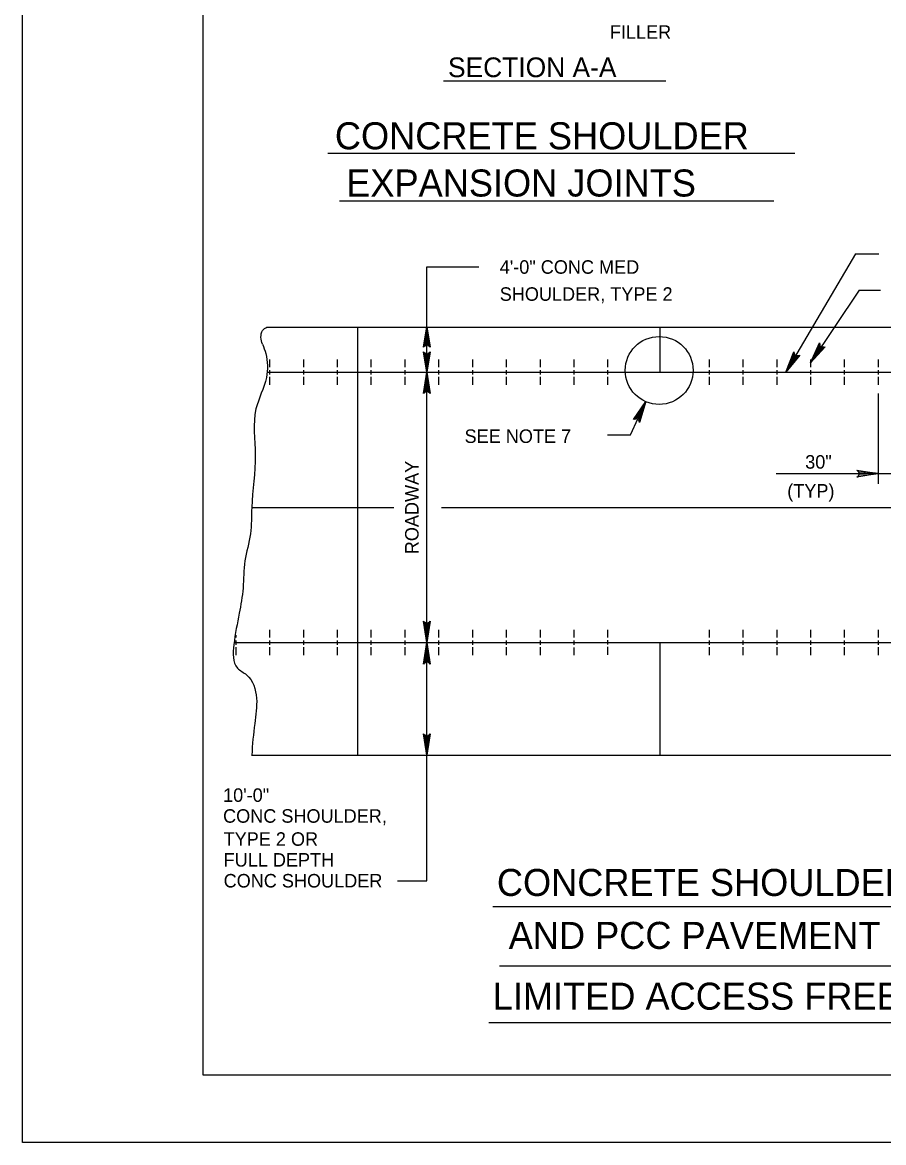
# Model space of a CAD drawing. Extents: x 638216 to 639962, y 297510 to 299292.
# Drawn here: x 638215.9 to 638406.9, y 297510.2 to 297758.8 of the extents above; entities that cross this region are included whole.
import ezdxf

# ---------------------------------------------------------------- set-up
doc = ezdxf.new("R2010")
doc.units = 0
for name, color, linetype in [('1', 7, 'Continuous'), ('2', 7, 'Continuous'), ('3', 7, 'Continuous'), ('PLT-BNDY', 7, 'Continuous')]:
    doc.layers.add(name, color=color, linetype=linetype)

msp = doc.modelspace()

# ---------------------------------------------------------------- linework, layer by layer
at = {"layer": '1'}
msp.add_lwpolyline([(639041.88, 297525.24), (639041.88, 298089.24), (638255.88, 298089.24), (638255.88, 297525.24), (639041.88, 297525.24), (639041.88, 297551.6), (638841.88, 297551.6), (638841.88, 297616.28), (639041.88, 297616.28), (639041.88, 297645.24), (638841.88, 297645.24), (638841.88, 297525.24), (638920.69, 297525.24), (638920.69, 297551.6), (638920.69, 297525.24), (638997.69, 297525.24), (638997.69, 297551.6), (638997.69, 297539.28), (639041.88, 297539.28)], dxfattribs=at)
msp.add_lwpolyline([(639041.88, 297525.24), (639041.88, 298089.24), (638255.88, 298089.24), (638255.88, 297525.24), (639041.88, 297525.24), (639041.88, 297551.6), (638841.88, 297551.6), (638841.88, 297616.28), (639041.88, 297616.28), (639041.88, 297645.24), (638841.88, 297645.24), (638841.88, 297525.24), (638920.69, 297525.24), (638920.69, 297551.6), (638920.69, 297525.24), (638997.69, 297525.24), (638997.69, 297551.6), (638997.69, 297539.28), (639041.88, 297539.28)], dxfattribs=at)
msp.add_lwpolyline([(639041.88, 297525.24), (639041.88, 298089.24), (638255.88, 298089.24), (638255.88, 297525.24), (639041.88, 297525.24), (639041.88, 297551.6), (638841.88, 297551.6), (638841.88, 297616.28), (639041.88, 297616.28), (639041.88, 297645.24), (638841.88, 297645.24), (638841.88, 297525.24), (638920.69, 297525.24), (638920.69, 297551.6), (638920.69, 297525.24), (638997.69, 297525.24), (638997.69, 297551.6), (638997.69, 297539.28), (639041.88, 297539.28)], dxfattribs=at)
at = {"layer": '2'}
for p, q in [((638309.27, 297745.82), (638358.65, 297745.82)), ((638283.62, 297729.81), (638387.26, 297729.81)), ((638286.22, 297719.24), (638382.55, 297719.24)), ((638400.7, 297707.43), (638385.27, 297681.23)), ((638400.7, 297707.43), (638405.83, 297707.43)), ((638305.6, 297691.26), (638305.6, 297704.56)), ((638305.6, 297704.56), (638317.17, 297704.56)), ((638401.52, 297699.43), (638390.69, 297683.31)), ((638401.52, 297699.43), (638406.2, 297699.43)), ((638270.14, 297691.19), (638603.98, 297691.19)), ((638290.3, 297596.19), (638290.3, 297691.19)), ((638305.6, 297681.21), (638305.6, 297691.26)), ((638357.35, 297681.19), (638357.35, 297691.19)), ((638270.78, 297682.3), (638270.78, 297684)), ((638278.28, 297682.3), (638278.28, 297684)), ((638285.78, 297682.3), (638285.78, 297684)), ((638293.28, 297682.3), (638293.28, 297684)), ((638300.78, 297682.3), (638300.78, 297684)), ((638308.28, 297682.3), (638308.28, 297684)), ((638315.78, 297682.3), (638315.78, 297684)), ((638323.28, 297682.3), (638323.28, 297684)), ((638330.78, 297682.3), (638330.78, 297684)), ((638338.28, 297682.3), (638338.28, 297684)), ((638345.78, 297682.3), (638345.78, 297684)), ((638368.28, 297682.3), (638368.28, 297684)), ((638375.78, 297682.3), (638375.78, 297684)), ((638383.28, 297682.3), (638383.28, 297684)), ((638390.78, 297682.3), (638390.78, 297684)), ((638398.28, 297682.3), (638398.28, 297684)), ((638405.78, 297682.3), (638405.78, 297684)), ((638270.23, 297681.19), (638604.59, 297681.19)), ((638270.78, 297680.69), (638270.78, 297681.66)), ((638278.28, 297680.69), (638278.28, 297681.66)), ((638285.78, 297680.69), (638285.78, 297681.66)), ((638293.28, 297680.69), (638293.28, 297681.66)), ((638300.78, 297680.69), (638300.78, 297681.66)), ((638305.6, 297651.23), (638305.6, 297681.21)), ((638308.28, 297680.69), (638308.28, 297681.66)), ((638315.78, 297680.69), (638315.78, 297681.66)), ((638323.28, 297680.69), (638323.28, 297681.66)), ((638330.78, 297680.69), (638330.78, 297681.66)), ((638338.28, 297680.69), (638338.28, 297681.66)), ((638345.78, 297680.69), (638345.78, 297681.66)), ((638368.28, 297680.69), (638368.28, 297681.66)), ((638375.78, 297680.69), (638375.78, 297681.66)), ((638383.28, 297680.69), (638383.28, 297681.66)), ((638390.78, 297680.69), (638390.78, 297681.66)), ((638398.28, 297680.69), (638398.28, 297681.66)), ((638405.78, 297680.69), (638405.78, 297681.66)), ((638270.78, 297678.38), (638270.78, 297680.15)), ((638278.28, 297678.38), (638278.28, 297680.15)), ((638285.78, 297678.38), (638285.78, 297680.15)), ((638293.28, 297678.38), (638293.28, 297680.15)), ((638300.78, 297678.38), (638300.78, 297680.15)), ((638308.28, 297678.38), (638308.28, 297680.15)), ((638315.78, 297678.38), (638315.78, 297680.15)), ((638323.28, 297678.38), (638323.28, 297680.15)), ((638330.78, 297678.38), (638330.78, 297680.15)), ((638338.28, 297678.38), (638338.28, 297680.15)), ((638345.78, 297678.38), (638345.78, 297680.15)), ((638368.28, 297678.38), (638368.28, 297680.15)), ((638375.78, 297678.38), (638375.78, 297680.15)), ((638383.28, 297678.38), (638383.28, 297680.15)), ((638390.78, 297678.38), (638390.78, 297680.15)), ((638398.28, 297678.38), (638398.28, 297680.15)), ((638405.78, 297678.38), (638405.78, 297680.15)), ((638405.78, 297656.44), (638405.78, 297676.5)), ((638350.8, 297667.27), (638354.15, 297674.67)), ((638345.66, 297667.27), (638350.8, 297667.27)), ((638383.1, 297658.7), (638409.46, 297658.7)), ((638266.87, 297651.19), (638298.27, 297651.19)), ((638305.6, 297621.21), (638305.6, 297651.23)), ((638308.85, 297651.19), (638603.68, 297651.19)), ((638270.78, 297622.3), (638270.78, 297624)), ((638278.28, 297622.3), (638278.28, 297624)), ((638285.78, 297622.3), (638285.78, 297624)), ((638293.28, 297622.3), (638293.28, 297624)), ((638300.78, 297622.3), (638300.78, 297624)), ((638308.28, 297622.3), (638308.28, 297624)), ((638315.78, 297622.3), (638315.78, 297624)), ((638323.28, 297622.3), (638323.28, 297624)), ((638330.78, 297622.3), (638330.78, 297624)), ((638338.28, 297622.3), (638338.28, 297624)), ((638345.78, 297622.3), (638345.78, 297624)), ((638368.28, 297622.3), (638368.28, 297624)), ((638375.78, 297622.3), (638375.78, 297624)), ((638383.28, 297622.3), (638383.28, 297624)), ((638390.78, 297622.3), (638390.78, 297624)), ((638398.28, 297622.3), (638398.28, 297624)), ((638405.78, 297622.3), (638405.78, 297624)), ((638262.88, 297621.19), (638602.13, 297621.19)), ((638263.28, 297622.3), (638263.28, 297622.83)), ((638263.28, 297620.69), (638263.28, 297621.66)), ((638270.78, 297620.69), (638270.78, 297621.66)), ((638278.28, 297620.69), (638278.28, 297621.66)), ((638285.78, 297620.69), (638285.78, 297621.66)), ((638293.28, 297620.69), (638293.28, 297621.66)), ((638300.78, 297620.69), (638300.78, 297621.66)), ((638305.6, 297596.2), (638305.6, 297621.21)), ((638308.28, 297620.69), (638308.28, 297621.66)), ((638315.78, 297620.69), (638315.78, 297621.66)), ((638323.28, 297620.69), (638323.28, 297621.66)), ((638330.78, 297620.69), (638330.78, 297621.66)), ((638338.25, 297620.68), (638338.25, 297621.65)), ((638345.77, 297620.76), (638345.77, 297621.73)), ((638357.35, 297596.19), (638357.35, 297621.19)), ((638368.28, 297620.69), (638368.28, 297621.66)), ((638375.78, 297620.69), (638375.78, 297621.66)), ((638383.28, 297620.69), (638383.28, 297621.66)), ((638390.78, 297620.69), (638390.78, 297621.66)), ((638398.28, 297620.69), (638398.28, 297621.66)), ((638405.78, 297620.69), (638405.78, 297621.66)), ((638263.28, 297618.38), (638263.28, 297620.15)), ((638270.78, 297618.38), (638270.78, 297620.15)), ((638278.28, 297618.38), (638278.28, 297620.15)), ((638285.78, 297618.38), (638285.78, 297620.15)), ((638293.28, 297618.38), (638293.28, 297620.15)), ((638300.78, 297618.38), (638300.78, 297620.15)), ((638308.28, 297618.38), (638308.28, 297620.15)), ((638315.78, 297618.38), (638315.78, 297620.15)), ((638323.28, 297618.38), (638323.28, 297620.15)), ((638330.78, 297618.38), (638330.78, 297620.15)), ((638338.25, 297618.37), (638338.25, 297620.14)), ((638345.77, 297618.45), (638345.77, 297620.22)), ((638368.28, 297618.38), (638368.28, 297620.15)), ((638375.78, 297618.38), (638375.78, 297620.15)), ((638383.28, 297618.38), (638383.28, 297620.15)), ((638390.78, 297618.38), (638390.78, 297620.15)), ((638398.28, 297618.38), (638398.28, 297620.15)), ((638405.78, 297618.38), (638405.78, 297620.15)), ((638266.73, 297596.19), (638600.13, 297596.19)), ((638305.6, 297568.36), (638305.6, 297596.2)), ((638299.07, 297568.36), (638305.6, 297568.36)), ((638320.26, 297562.64), (638575.86, 297562.64)), ((638321.73, 297549.46), (638572.46, 297549.46)), ((638319.33, 297536.91), (638579.89, 297536.91))]:
    msp.add_line(p, q, dxfattribs=at)
for points in [[(638305.05, 297686.94), (638305.37, 297687.1), (638305.6, 297691.25), (638305.05, 297686.94), (638304.86, 297686.72), (638305.6, 297691.25), (638305.8, 297687.1), (638306.11, 297686.95), (638305.6, 297691.25), (638306.32, 297686.72), (638306.11, 297686.95)], [(638306.14, 297685.52), (638305.82, 297685.36), (638305.59, 297681.21), (638306.14, 297685.52), (638306.32, 297685.74), (638305.59, 297681.21), (638305.39, 297685.36), (638305.08, 297685.51), (638305.59, 297681.21), (638304.87, 297685.74), (638305.08, 297685.51)], [(638388.07, 297684.85), (638387.7, 297684.88), (638385.27, 297681.23), (638388.07, 297684.85), (638388.36, 297684.95), (638385.27, 297681.23), (638387.31, 297685.1), (638387.11, 297685.41), (638385.27, 297681.23), (638387.04, 297685.73), (638387.11, 297685.41)], [(638393.7, 297686.76), (638393.33, 297686.8), (638390.69, 297683.31), (638393.7, 297686.76), (638393.99, 297686.84), (638390.69, 297683.31), (638392.95, 297687.05), (638392.77, 297687.37), (638390.69, 297683.31), (638392.72, 297687.69), (638392.77, 297687.37)], [(638305.03, 297676.67), (638305.35, 297676.84), (638305.6, 297681.21), (638305.03, 297676.67), (638304.83, 297676.44), (638305.6, 297681.21), (638305.81, 297676.85), (638306.14, 297676.69), (638305.6, 297681.21), (638306.35, 297676.44), (638306.14, 297676.69)], [(638351.7, 297670.8), (638352.07, 297670.82), (638354.15, 297674.67), (638351.7, 297670.8), (638351.42, 297670.68), (638354.15, 297674.67), (638352.49, 297670.63), (638352.71, 297670.34), (638354.15, 297674.67), (638352.81, 297670.03), (638352.71, 297670.34)], [(638401.24, 297659.27), (638401.41, 297658.94), (638405.78, 297658.7), (638401.24, 297659.27), (638401.01, 297659.47), (638405.78, 297658.7), (638401.41, 297658.48), (638401.25, 297658.16), (638405.78, 297658.7), (638401.01, 297657.94), (638401.25, 297658.16)], [(638306.17, 297625.75), (638305.84, 297625.58), (638305.6, 297621.21), (638306.17, 297625.75), (638306.36, 297625.98), (638305.6, 297621.21), (638305.38, 297625.58), (638305.05, 297625.73), (638305.6, 297621.21), (638304.84, 297625.98), (638305.05, 297625.73)], [(638305.03, 297616.66), (638305.35, 297616.84), (638305.6, 297621.21), (638305.03, 297616.66), (638304.83, 297616.43), (638305.6, 297621.21), (638305.81, 297616.84), (638306.14, 297616.68), (638305.6, 297621.21), (638306.35, 297616.43), (638306.14, 297616.68)], [(638306.17, 297600.74), (638305.84, 297600.57), (638305.6, 297596.2), (638306.17, 297600.74), (638306.36, 297600.97), (638305.6, 297596.2), (638305.38, 297600.56), (638305.05, 297600.73), (638305.6, 297596.2), (638304.84, 297600.97), (638305.05, 297600.73)]]:
    msp.add_lwpolyline(points, dxfattribs=at)
msp.add_circle((638357.14, 297681.59), 7.53, dxfattribs=at)
for points in [[(638269.14, 297687.45), (638268.81, 297688.94), (638269.18, 297690.45), (638270.14, 297691.19)], [(638269.14, 297687.45), (638269.87, 297685.34), (638270.01, 297680.03), (638267.7, 297673.06), (638267.55, 297662.81), (638266.75, 297651.19), (638266.46, 297645.33), (638265.24, 297639.31), (638264.82, 297633.3), (638264, 297627.7), (638262.78, 297620.73), (638263.59, 297615.54), (638265.63, 297614.03), (638267.82, 297608.85), (638267.41, 297603.25), (638266.75, 297596.19)]]:
    msp.add_spline(points, degree=3, dxfattribs=at)
at = {"layer": 'PLT-BNDY'}
msp.add_lwpolyline([(638215.88, 298104.24), (639056.88, 298104.24), (639056.88, 297510.24), (638215.88, 297510.24)], close=True, dxfattribs=at)

# ---------------------------------------------------------------- texts
at = {"layer": '2'}
for s, p in [('TYPE 2 OR', (638260.52, 297576.1)), ('FULL DEPTH', (638260.52, 297571.48)), ('CONC SHOULDER', (638260.52, 297566.85))]:
    msp.add_text(s, height=3, dxfattribs=at).set_placement(p)
at = {"layer": '3'}
for s, height, p in [(' FILLER', 3, (638345.09, 297755.18)), ('SECTION A-A', 4.375, (638310.29, 297746.67)), ('CONCRETE SHOULDER', 6, (638285.2, 297730.66)), ('EXPANSION JOINTS', 6, (638287.72, 297720.18)), ('4\'-0" CONC MED', 3, (638321.77, 297703.04)), ('SHOULDER, TYPE 2', 3, (638321.77, 297697.04)), ('SEE NOTE 7', 3, (638313.97, 297665.5)), ('30"', 3, (638389.53, 297659.79)), ('(TYP)', 3, (638385.55, 297653.38)), ('10\'-0"', 3, (638260.4, 297585.85)), ('CONC SHOULDER,', 3, (638260.4, 297581.22)), ('CONCRETE SHOULDERS ADJACENT TO     PAVEMENT', 6, (638321.14, 297564.97)), ('AND PCC PAVEMENT FOR INTERSTATE AND OTHER', 6, (638323.76, 297553.22)), ('LIMITED ACCESS FREEWAYS, ARTERIALS AND RAMPS', 6, (638320.22, 297539.73))]:
    msp.add_text(s, height=height, dxfattribs=at).set_placement(p)
msp.add_text('ROADWAY', height=3, rotation=90, dxfattribs=at).set_placement((638303.77, 297640.81))

doc.saveas('drawing.dxf')
